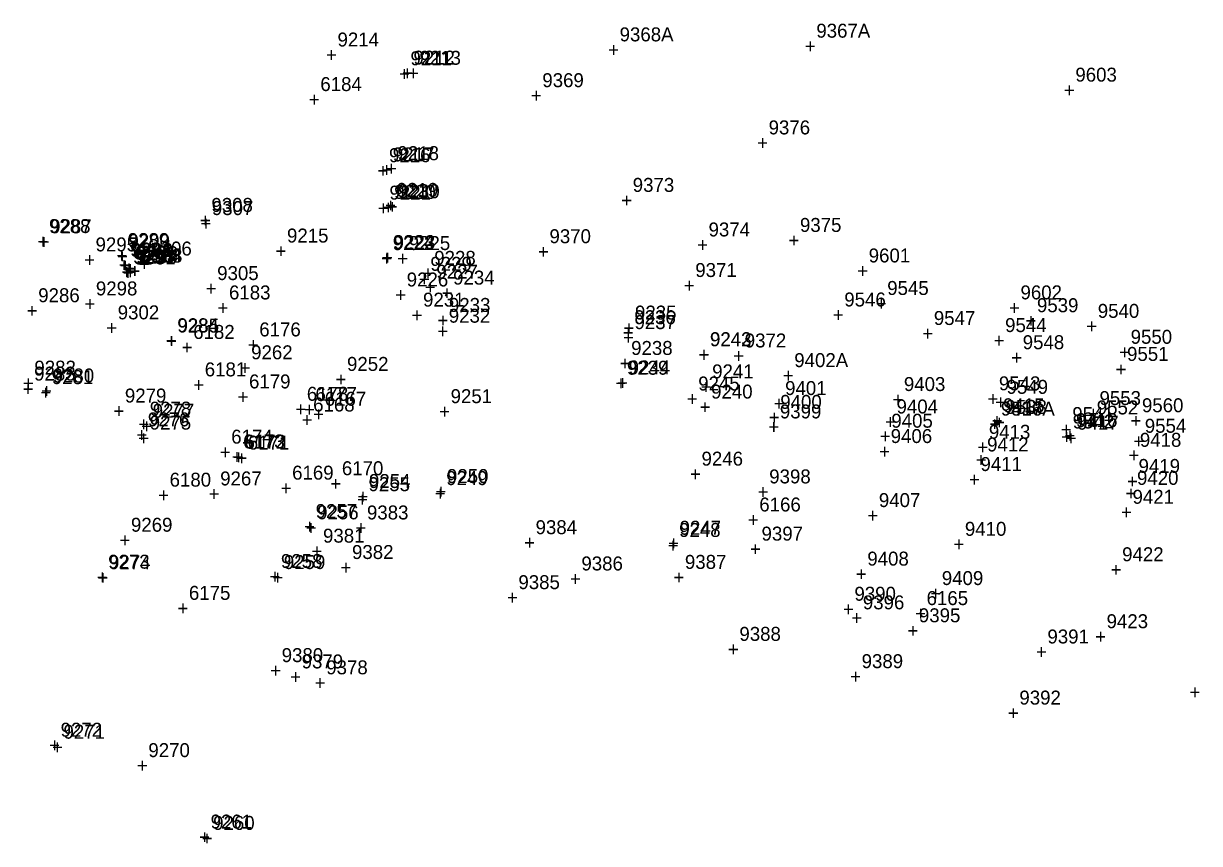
# Model space of a CAD drawing. Extents: x 1136220 to 1137808, y 528804 to 531215.
# Drawn here: x 1136283.7 to 1136494.6, y 529226.6 to 529373.6 of the extents above; entities that cross this region are included whole.
import ezdxf

# ---------------------------------------------------------------- set-up
doc = ezdxf.new("R2010")
doc.units = 0
for name, color, linetype in [('S_Bridge_Abutment_Bottom', 7, 'Continuous'), ('S_Buildings', 7, 'Continuous'), ('S_Curb_Type_3', 7, 'Continuous'), ('S_Drainage_CB', 7, 'Continuous'), ('S_Drainage_Culvert_Top', 7, 'Continuous'), ('S_Drainage_Invert', 7, 'Continuous'), ('S_Drainage_Sump', 7, 'Continuous'), ('S_Fencing_ChainLink', 7, 'Continuous'), ('S_Fencing_Gate', 7, 'Continuous'), ('S_Fencing_Picket', 7, 'Continuous'), ('S_Ground_Elevation', 7, 'Continuous'), ('S_Ground_LevelString', 7, 'Continuous'), ('S_Guardrail_Beam', 7, 'Continuous'), ('S_Property_IronPipeFound', 7, 'Continuous'), ('S_Roadway_Centerline', 7, 'Continuous'), ('S_Roadway_Drive_Paved', 7, 'Continuous'), ('S_Roadway_Edge_Pavement', 7, 'Continuous'), ('S_Roadway_Sidewalks', 7, 'Continuous'), ('S_Traffic_Sign_SinglePost', 7, 'Continuous'), ('S_Trees_Bush', 7, 'Continuous'), ('S_Trees_Decid_Pay', 7, 'Continuous'), ('S_Trees_HedgeLine', 7, 'Continuous'), ('S_Trees_TreeLine', 7, 'Continuous'), ('S_Utilities_Gas_Gate', 7, 'Continuous'), ('S_Utilities_GuyWire3', 7, 'Continuous'), ('S_Utilities_Pole_Power', 7, 'Continuous'), ('S_Utilities_UG_Gas_Line', 7, 'Continuous'), ('S_Utilities_UG_Sanitary_MH', 7, 'Continuous'), ('S_Utilities_UG_Sanitary_Sewer', 7, 'Continuous'), ('S_Utilities_UG_Water_Gate', 7, 'Continuous')]:
    doc.layers.add(name, color=color, linetype=linetype)

msp = doc.modelspace()

# ---------------------------------------------------------------- texts
at = {"layer": 'S_Bridge_Abutment_Bottom'}
for s, p in [('9223', (1136350.08, 529333.16)), ('+', (1136348.01, 529330.41))]:
    msp.add_text(s, height=2.5, dxfattribs=at).set_placement(p)
at = {"layer": 'S_Buildings'}
for s, p in [('9603', (1136472.33, 529363.19)), ('+', (1136470.27, 529360.44)), ('9601', (1136435.27, 529330.78)), ('+', (1136433.21, 529328.03)), ('9602', (1136462.49, 529324.16)), ('+', (1136460.43, 529321.41))]:
    msp.add_text(s, height=2.5, dxfattribs=at).set_placement(p)
at = {"layer": 'S_Curb_Type_3'}
for s, p in [('9212', (1136353.63, 529366.24)), ('+', (1136351.57, 529363.49)), ('9217', (1136349.92, 529348.89)), ('+', (1136347.86, 529346.14)), ('9308', (1136317.39, 529339.84)), ('9288', (1136288.27, 529336.06)), ('+', (1136315.33, 529337.09)), ('+', (1136286.21, 529333.31)), ('9289', (1136302.4, 529333.54)), ('9224', (1136349.96, 529333.18)), ('+', (1136300.34, 529330.79)), ('+', (1136347.89, 529330.43)), ('9283', (1136285.6, 529309.6)), ('9281', (1136288.78, 529308.97)), ('+', (1136283.54, 529306.85)), ('+', (1136286.72, 529306.22)), ('9278', (1136306.34, 529303.32)), ('+', (1136304.28, 529300.57)), ('9276', (1136306, 529301.4)), ('+', (1136303.94, 529298.65)), ('9255', (1136345.57, 529289.78)), ('9249', (1136359.51, 529290.87)), ('+', (1136357.45, 529288.12)), ('+', (1136343.51, 529287.03)), ('9256', (1136336.36, 529284.73)), ('+', (1136334.3, 529281.98)), ('9248', (1136401.27, 529281.57)), ('+', (1136399.21, 529278.82)), ('9273', (1136298.89, 529275.89)), ('9259', (1136330.39, 529275.82)), ('+', (1136296.83, 529273.14)), ('+', (1136328.33, 529273.07)), ('9272', (1136290.35, 529245.77)), ('+', (1136288.29, 529243.02)), ('9260', (1136317.71, 529229.06)), ('+', (1136315.65, 529226.31))]:
    msp.add_text(s, height=2.5, dxfattribs=at).set_placement(p)
at = {"layer": 'S_Drainage_CB'}
for s, p in [('9291', (1136303.72, 529331.26)), ('+', (1136301.66, 529328.51)), ('9269', (1136302.97, 529282.51)), ('+', (1136300.91, 529279.76))]:
    msp.add_text(s, height=2.5, dxfattribs=at).set_placement(p)
at = {"layer": 'S_Drainage_Culvert_Top'}
for s, p in [('9295', (1136296.62, 529332.76)), ('9294', (1136302.82, 529331.86)), ('+', (1136294.56, 529330.01)), ('9297', (1136303.36, 529330.53)), ('9301', (1136303.54, 529330.42)), ('9304', (1136304.69, 529330.8)), ('+', (1136300.76, 529329.11)), ('+', (1136301.29, 529327.78)), ('+', (1136302.63, 529328.05)), ('9305', (1136318.43, 529327.62)), ('+', (1136301.48, 529327.67)), ('9298', (1136296.68, 529324.87)), ('+', (1136316.37, 529324.87)), ('+', (1136294.62, 529322.12)), ('9302', (1136300.59, 529320.58)), ('+', (1136298.53, 529317.83))]:
    msp.add_text(s, height=2.5, dxfattribs=at).set_placement(p)
at = {"layer": 'S_Drainage_Invert'}
for s, p in [('9293', (1136303.03, 529331.76)), ('9296', (1136303.3, 529330.6)), ('9299', (1136303.92, 529330.54)), ('9303', (1136304.76, 529330.76)), ('+', (1136300.97, 529329.01)), ('+', (1136301.24, 529327.85)), ('+', (1136301.86, 529327.79)), ('+', (1136302.69, 529328.01))]:
    msp.add_text(s, height=2.5, dxfattribs=at).set_placement(p)
at = {"layer": 'S_Drainage_Sump'}
for s, p in [('9292', (1136303.96, 529331.18)), ('+', (1136301.9, 529328.43))]:
    msp.add_text(s, height=2.5, dxfattribs=at).set_placement(p)
at = {"layer": 'S_Fencing_ChainLink'}
for s, p in [('9378', (1136337.99, 529256.95)), ('+', (1136335.92, 529254.2))]:
    msp.add_text(s, height=2.5, dxfattribs=at).set_placement(p)
at = {"layer": 'S_Fencing_Gate'}
for s, p in [('9415', (1136459.37, 529303.92)), ('+', (1136457.31, 529301.17)), ('9416', (1136472.44, 529301.26)), ('+', (1136470.38, 529298.51))]:
    msp.add_text(s, height=2.5, dxfattribs=at).set_placement(p)
at = {"layer": 'S_Fencing_Picket'}
for s, p in [('9227', (1136357.74, 529327.87)), ('+', (1136355.67, 529325.12)), ('9236', (1136393.23, 529319.71)), ('+', (1136391.17, 529316.96)), ('9243', (1136406.82, 529315.78)), ('+', (1136404.76, 529313.03)), ('9402', (1136421.92, 529312.02)), ('+', (1136419.86, 529309.27)), ('9403', (1136441.58, 529307.73)), ('+', (1136439.52, 529304.98)), ('9418', (1136483.9, 529297.73)), ('+', (1136481.84, 529294.98))]:
    msp.add_text(s, height=2.5, dxfattribs=at).set_placement(p)
at = {"layer": 'S_Ground_Elevation'}
for s, p in [('9368A', (1136390.6, 529370.41)), ('9367A', (1136425.88, 529371.07)), ('+', (1136423.81, 529368.32)), ('9213', (1136354.71, 529366.21)), ('+', (1136388.54, 529367.66)), ('+', (1136352.65, 529363.46)), ('9218', (1136350.77, 529349.12)), ('+', (1136348.71, 529346.37)), ('9219', (1136350.62, 529342.53)), ('9373', (1136392.95, 529343.43)), ('+', (1136390.89, 529340.68)), ('+', (1136348.56, 529339.78)), ('9375', (1136422.94, 529336.25)), ('9374', (1136406.55, 529335.44)), ('+', (1136404.49, 529332.69)), ('+', (1136420.88, 529333.5)), ('9546', (1136430.89, 529322.89)), ('9235', (1136393.36, 529320.54)), ('+', (1136428.83, 529320.14)), ('9547', (1136446.95, 529319.57)), ('+', (1136391.3, 529317.79)), ('+', (1136444.89, 529316.82)), ('9548', (1136462.89, 529315.23)), ('9550', (1136482.24, 529316.2)), ('+', (1136480.18, 529313.45)), ('9551', (1136481.6, 529313.13)), ('+', (1136460.83, 529312.48)), ('+', (1136479.54, 529310.38)), ('9549', (1136459.99, 529307.23)), ('9553', (1136476.66, 529305.22)), ('+', (1136457.93, 529304.48)), ('+', (1136474.59, 529302.47)), ('9383', (1136345.29, 529284.71)), ('+', (1136343.23, 529281.96)), ('9384', (1136375.53, 529282.07)), ('9381', (1136337.41, 529280.55)), ('+', (1136373.47, 529279.32)), ('+', (1136335.35, 529277.8)), ('9382', (1136342.61, 529277.62)), ('9387', (1136402.31, 529275.85)), ('+', (1136340.54, 529274.87)), ('+', (1136400.25, 529273.1)), ('9385', (1136372.45, 529272.22)), ('+', (1136370.39, 529269.47)), ('9390', (1136432.71, 529270.14)), ('+', (1136430.65, 529267.39)), ('9388', (1136412.08, 529262.95)), ('9391', (1136467.32, 529262.48)), ('9380', (1136330, 529259.14)), ('+', (1136410.02, 529260.2)), ('9389', (1136434, 529258.06)), ('+', (1136465.26, 529259.73)), ('+', (1136327.94, 529256.39)), ('+', (1136431.94, 529255.31)), ('9392', (1136462.29, 529251.53)), ('+', (1136492.8, 529252.53)), ('+', (1136460.23, 529248.78))]:
    msp.add_text(s, height=2.5, dxfattribs=at).set_placement(p)
at = {"layer": 'S_Ground_LevelString'}
for s, p in [('9233', (1136359.99, 529321.91)), ('+', (1136357.93, 529319.16)), ('9238', (1136392.67, 529314.2)), ('+', (1136390.61, 529311.45)), ('9244', (1136392.22, 529310.71)), ('9241', (1136407.2, 529310)), ('+', (1136390.16, 529307.96)), ('9245', (1136404.7, 529307.83)), ('+', (1136405.14, 529307.25)), ('9401', (1136420.28, 529307.01)), ('+', (1136402.64, 529305.08)), ('9400', (1136419.41, 529304.53)), ('+', (1136418.22, 529304.26)), ('9404', (1136440.26, 529303.71)), ('+', (1136417.35, 529301.78)), ('+', (1136438.2, 529300.96)), ('9405', (1136439.33, 529301.16)), ('+', (1136437.27, 529298.41)), ('9413', (1136456.82, 529299.17)), ('+', (1136454.75, 529296.42)), ('9412', (1136456.5, 529296.9)), ('+', (1136454.44, 529294.15)), ('9419', (1136483.66, 529293.05)), ('+', (1136481.59, 529290.3)), ('9420', (1136483.38, 529290.91)), ('+', (1136481.32, 529288.16))]:
    msp.add_text(s, height=2.5, dxfattribs=at).set_placement(p)
at = {"layer": 'S_Guardrail_Beam'}
for s, p in [('9220', (1136350.18, 529342.17)), ('+', (1136348.12, 529339.42)), ('9225', (1136352.78, 529333)), ('+', (1136350.72, 529330.25))]:
    msp.add_text(s, height=2.5, dxfattribs=at).set_placement(p)
at = {"layer": 'S_Property_IronPipeFound'}
for s, p in [('9228', (1136357.36, 529330.35)), ('+', (1136355.29, 529327.6))]:
    msp.add_text(s, height=2.5, dxfattribs=at).set_placement(p)
at = {"layer": 'S_Roadway_Centerline'}
for s, p in [('9214', (1136340.01, 529369.49)), ('+', (1136337.95, 529366.74)), ('9215', (1136330.95, 529334.35)), ('+', (1136328.88, 529331.6)), ('9286', (1136286.34, 529323.65)), ('+', (1136284.27, 529320.9)), ('9284', (1136311.27, 529318.27)), ('9285', (1136311.33, 529318.22)), ('+', (1136309.21, 529315.52)), ('+', (1136309.27, 529315.47)), ('9262', (1136324.52, 529313.42)), ('9252', (1136341.71, 529311.34)), ('+', (1136322.46, 529310.67)), ('+', (1136339.65, 529308.59)), ('9251', (1136360.29, 529305.56)), ('+', (1136358.23, 529302.81)), ('9246', (1136405.29, 529294.36)), ('9267', (1136318.97, 529290.81)), ('+', (1136403.23, 529291.61)), ('9398', (1136417.43, 529291.17)), ('+', (1136316.91, 529288.06)), ('+', (1136415.36, 529288.42)), ('9407', (1136437.09, 529286.93)), ('+', (1136435.03, 529284.18)), ('9410', (1136452.52, 529281.78)), ('+', (1136450.46, 529279.03)), ('9422', (1136480.72, 529277.22)), ('+', (1136478.66, 529274.47)), ('9270', (1136306.09, 529242.11)), ('+', (1136304.03, 529239.36))]:
    msp.add_text(s, height=2.5, dxfattribs=at).set_placement(p)
at = {"layer": 'S_Roadway_Drive_Paved'}
for s, p in [('9539', (1136465.44, 529321.86)), ('9540', (1136476.35, 529320.85)), ('+', (1136463.38, 529319.11)), ('+', (1136474.28, 529318.1)), ('9537', (1136458.97, 529303.33)), ('9538', (1136459.78, 529303.63)), ('9541', (1136471.78, 529302.35)), ('+', (1136456.91, 529300.58)), ('+', (1136457.72, 529300.88)), ('9542', (1136471.85, 529301.02)), ('+', (1136469.72, 529299.6)), ('+', (1136469.78, 529298.27))]:
    msp.add_text(s, height=2.5, dxfattribs=at).set_placement(p)
at = {"layer": 'S_Roadway_Edge_Pavement'}
for s, p in [('9211', (1136353.09, 529366.12)), ('+', (1136351.03, 529363.37)), ('9216', (1136349.24, 529348.75)), ('+', (1136347.18, 529346)), ('9221', (1136349.32, 529342.04)), ('9307', (1136317.48, 529339.27)), ('+', (1136347.25, 529339.29)), ('9287', (1136288.47, 529336)), ('+', (1136315.42, 529336.52)), ('+', (1136286.41, 529333.25)), ('9290', (1136302.52, 529333.38)), ('9306', (1136306.44, 529332.02)), ('9222', (1136349.91, 529332.99)), ('+', (1136300.46, 529330.63)), ('+', (1136347.85, 529330.24)), ('+', (1136304.38, 529329.27)), ('9226', (1136352.42, 529326.47)), ('+', (1136350.36, 529323.72)), ('9231', (1136355.35, 529322.86)), ('+', (1136353.29, 529320.11)), ('9232', (1136359.96, 529319.98)), ('+', (1136357.9, 529317.23)), ('9282', (1136285.65, 529310.67)), ('9239', (1136391.91, 529310.65)), ('9280', (1136288.93, 529309.26)), ('+', (1136283.59, 529307.92)), ('+', (1136389.85, 529307.9)), ('9240', (1136407.01, 529306.38)), ('+', (1136286.87, 529306.51)), ('9279', (1136301.88, 529305.67)), ('+', (1136299.82, 529302.92)), ('9277', (1136306.87, 529302.94)), ('+', (1136404.95, 529303.63)), ('9399', (1136419.34, 529302.82)), ('9275', (1136306.33, 529300.81)), ('+', (1136304.81, 529300.19)), ('+', (1136417.28, 529300.07)), ('9406', (1136439.21, 529298.41)), ('+', (1136304.27, 529298.06)), ('+', (1136437.15, 529295.66)), ('9411', (1136455.31, 529293.39)), ('9254', (1136345.65, 529290.35)), ('9250', (1136359.64, 529291.24)), ('+', (1136453.25, 529290.64)), ('+', (1136357.58, 529288.49)), ('9421', (1136482.58, 529287.52)), ('+', (1136343.58, 529287.6)), ('9257', (1136336.09, 529284.96)), ('+', (1136480.52, 529284.77)), ('+', (1136334.03, 529282.21)), ('9247', (1136401.36, 529281.97)), ('9397', (1136416.05, 529280.92)), ('+', (1136399.3, 529279.22)), ('+', (1136413.99, 529278.17)), ('9274', (1136299.03, 529275.79)), ('9258', (1136329.86, 529276.01)), ('9408', (1136435.02, 529276.44)), ('+', (1136296.97, 529273.04)), ('+', (1136327.8, 529273.26)), ('+', (1136432.96, 529273.69)), ('9409', (1136448.38, 529272.95)), ('+', (1136446.32, 529270.2)), ('9423', (1136477.93, 529265.22)), ('+', (1136475.87, 529262.47)), ('9271', (1136290.87, 529245.41)), ('+', (1136288.8, 529242.66)), ('9261', (1136317.25, 529229.3)), ('+', (1136315.19, 529226.55))]:
    msp.add_text(s, height=2.5, dxfattribs=at).set_placement(p)
at = {"layer": 'S_Roadway_Sidewalks'}
for s, p in [('9234', (1136360.74, 529326.81)), ('+', (1136358.68, 529324.06)), ('9237', (1136393.27, 529318.83)), ('+', (1136391.21, 529316.08)), ('9242', (1136406.79, 529315.75)), ('+', (1136404.73, 529313)), ('9402A', (1136421.92, 529312.02)), ('+', (1136419.86, 529309.27)), ('9416A', (1136458.97, 529303.33)), ('+', (1136456.91, 529300.58)), ('9417', (1136472.66, 529300.8)), ('+', (1136470.6, 529298.05))]:
    msp.add_text(s, height=2.5, dxfattribs=at).set_placement(p)
at = {"layer": 'S_Traffic_Sign_SinglePost'}
for s, p in [('9230', (1136350.9, 529342.29)), ('+', (1136348.84, 529339.54)), ('9229', (1136356.66, 529329.28)), ('+', (1136354.6, 529326.53))]:
    msp.add_text(s, height=2.5, dxfattribs=at).set_placement(p)
at = {"layer": 'S_Trees_Bush'}
for s, p in [('9545', (1136438.59, 529324.95)), ('+', (1136436.53, 529322.2)), ('9544', (1136459.73, 529318.3)), ('+', (1136457.67, 529315.55)), ('9543', (1136458.62, 529307.86)), ('+', (1136456.56, 529305.11))]:
    msp.add_text(s, height=2.5, dxfattribs=at).set_placement(p)
at = {"layer": 'S_Trees_Decid_Pay'}
for s, p in [('9376', (1136417.32, 529353.73)), ('+', (1136415.26, 529350.98)), ('9560', (1136484.27, 529303.93)), ('+', (1136482.21, 529301.18)), ('9386', (1136383.75, 529275.57)), ('+', (1136381.69, 529272.82))]:
    msp.add_text(s, height=2.5, dxfattribs=at).set_placement(p)
at = {"layer": 'S_Trees_HedgeLine'}
for s, p in [('9552', (1136476.17, 529303.54)), ('+', (1136474.11, 529300.79)), ('9554', (1136484.78, 529300.25)), ('+', (1136482.72, 529297.5))]:
    msp.add_text(s, height=2.5, dxfattribs=at).set_placement(p)
at = {"layer": 'S_Trees_TreeLine'}
for s, p in [('9369', (1136376.74, 529362.2)), ('+', (1136374.68, 529359.45)), ('9370', (1136378.02, 529334.23)), ('+', (1136375.96, 529331.48)), ('9371', (1136404.17, 529328.17)), ('+', (1136402.11, 529325.42)), ('9372', (1136413.04, 529315.54)), ('+', (1136410.97, 529312.79)), ('9379', (1136333.58, 529258.01)), ('+', (1136331.52, 529255.26))]:
    msp.add_text(s, height=2.5, dxfattribs=at).set_placement(p)
at = {"layer": 'S_Utilities_Gas_Gate'}
for s, p in [('6172', (1136323.35, 529297.38)), ('+', (1136321.29, 529294.63))]:
    msp.add_text(s, height=2.5, dxfattribs=at).set_placement(p)
at = {"layer": 'S_Utilities_GuyWire3'}
for s, p in [('9396', (1136434.22, 529268.6)), ('+', (1136432.16, 529265.85))]:
    msp.add_text(s, height=2.5, dxfattribs=at).set_placement(p)
at = {"layer": 'S_Utilities_Pole_Power'}
for s, p in [('9395', (1136444.27, 529266.28)), ('+', (1136442.21, 529263.53))]:
    msp.add_text(s, height=2.5, dxfattribs=at).set_placement(p)
at = {"layer": 'S_Utilities_UG_Gas_Line'}
for s, p in [('6184', (1136336.93, 529361.5)), ('+', (1136334.87, 529358.75)), ('6176', (1136325.98, 529317.52)), ('+', (1136323.92, 529314.77)), ('6174', (1136320.95, 529298.3)), ('6173', (1136323.08, 529297.45)), ('6171', (1136323.92, 529297.23)), ('+', (1136318.89, 529295.55)), ('+', (1136321.02, 529294.7)), ('+', (1136321.86, 529294.48)), ('6170', (1136340.79, 529292.64)), ('+', (1136338.73, 529289.89)), ('6175', (1136313.36, 529270.3)), ('6165', (1136445.65, 529269.36)), ('+', (1136311.3, 529267.55)), ('+', (1136443.59, 529266.61))]:
    msp.add_text(s, height=2.5, dxfattribs=at).set_placement(p)
at = {"layer": 'S_Utilities_UG_Sanitary_MH'}
for s, p in [('6177', (1136336.05, 529305.93)), ('+', (1136333.99, 529303.18))]:
    msp.add_text(s, height=2.5, dxfattribs=at).set_placement(p)
at = {"layer": 'S_Utilities_UG_Sanitary_Sewer'}
for s, p in [('6179', (1136324.14, 529308.2)), ('+', (1136322.08, 529305.45)), ('6178', (1136334.51, 529305.98)), ('6168', (1136335.64, 529304.06)), ('6167', (1136337.71, 529305.1)), ('+', (1136332.45, 529303.23)), ('+', (1136333.58, 529301.31)), ('+', (1136335.64, 529302.35)), ('6169', (1136331.87, 529291.85)), ('+', (1136329.81, 529289.1)), ('6166', (1136415.65, 529286.14)), ('+', (1136413.59, 529283.39))]:
    msp.add_text(s, height=2.5, dxfattribs=at).set_placement(p)
at = {"layer": 'S_Utilities_UG_Water_Gate'}
for s, p in [('6183', (1136320.55, 529324.15)), ('+', (1136318.49, 529321.4)), ('6182', (1136314.13, 529317.07)), ('+', (1136312.07, 529314.32)), ('6181', (1136316.2, 529310.36)), ('+', (1136314.14, 529307.61)), ('6180', (1136309.9, 529290.59)), ('+', (1136307.84, 529287.84))]:
    msp.add_text(s, height=2.5, dxfattribs=at).set_placement(p)

doc.saveas('drawing.dxf')
